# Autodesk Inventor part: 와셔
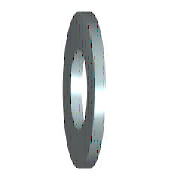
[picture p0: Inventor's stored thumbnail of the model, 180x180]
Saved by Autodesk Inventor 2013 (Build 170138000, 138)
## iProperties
IsCustomPart: 1
Created: 2012-02
Part Number: 와셔
Material: 강철, 연강
Description: 평면 와셔
Document SubType Name: Modeling
Standard: KS B 1326
Designer: mduedu
Standards Organization: KS
Language: ko-KR
Size Designation: 8x15.5
Categories: <MemberInstance><Categories><Category DisplayName="조임쇠" InternalName="e4da775c-781d-43d5-af7c-5136215cf5a6" Mnemonic="FSTN"><Category DisplayName="와셔" InternalN
Density: 1 g/cm^3
Author: mduedu
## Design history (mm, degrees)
sketch "스케치"
  geometry: C1 r 7.75 at (0, 0); C2 r 4.2 at (0, 0); 1 further point
  constraints: 2 centre point, 2 coincident
  dimensions: "d0" = 8.4 diameter of C2 (= SD1); "d1" = 15.5 diameter of C1 (= SD2)
extrude "본체" new body sketch "스케치" distance "d2" = 1.6 (= SD); taper "d3" = 0 deg
workaxis "Work Axis1"
workplane "Work Plane1"
body "Solid1"
other parameters: "SD1" = 8.4 [user parameter; used in 1 equation term], "SD2" = 15.5 [user parameter; used in 1 equation term], "SD" = 1.6 [user parameter; used in 1 equation term], "d4" = 0, "d5" = 0, "d6" = 0, "d7" = 0, "NND" = 8 [user parameter]
